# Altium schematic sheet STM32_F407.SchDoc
size A2
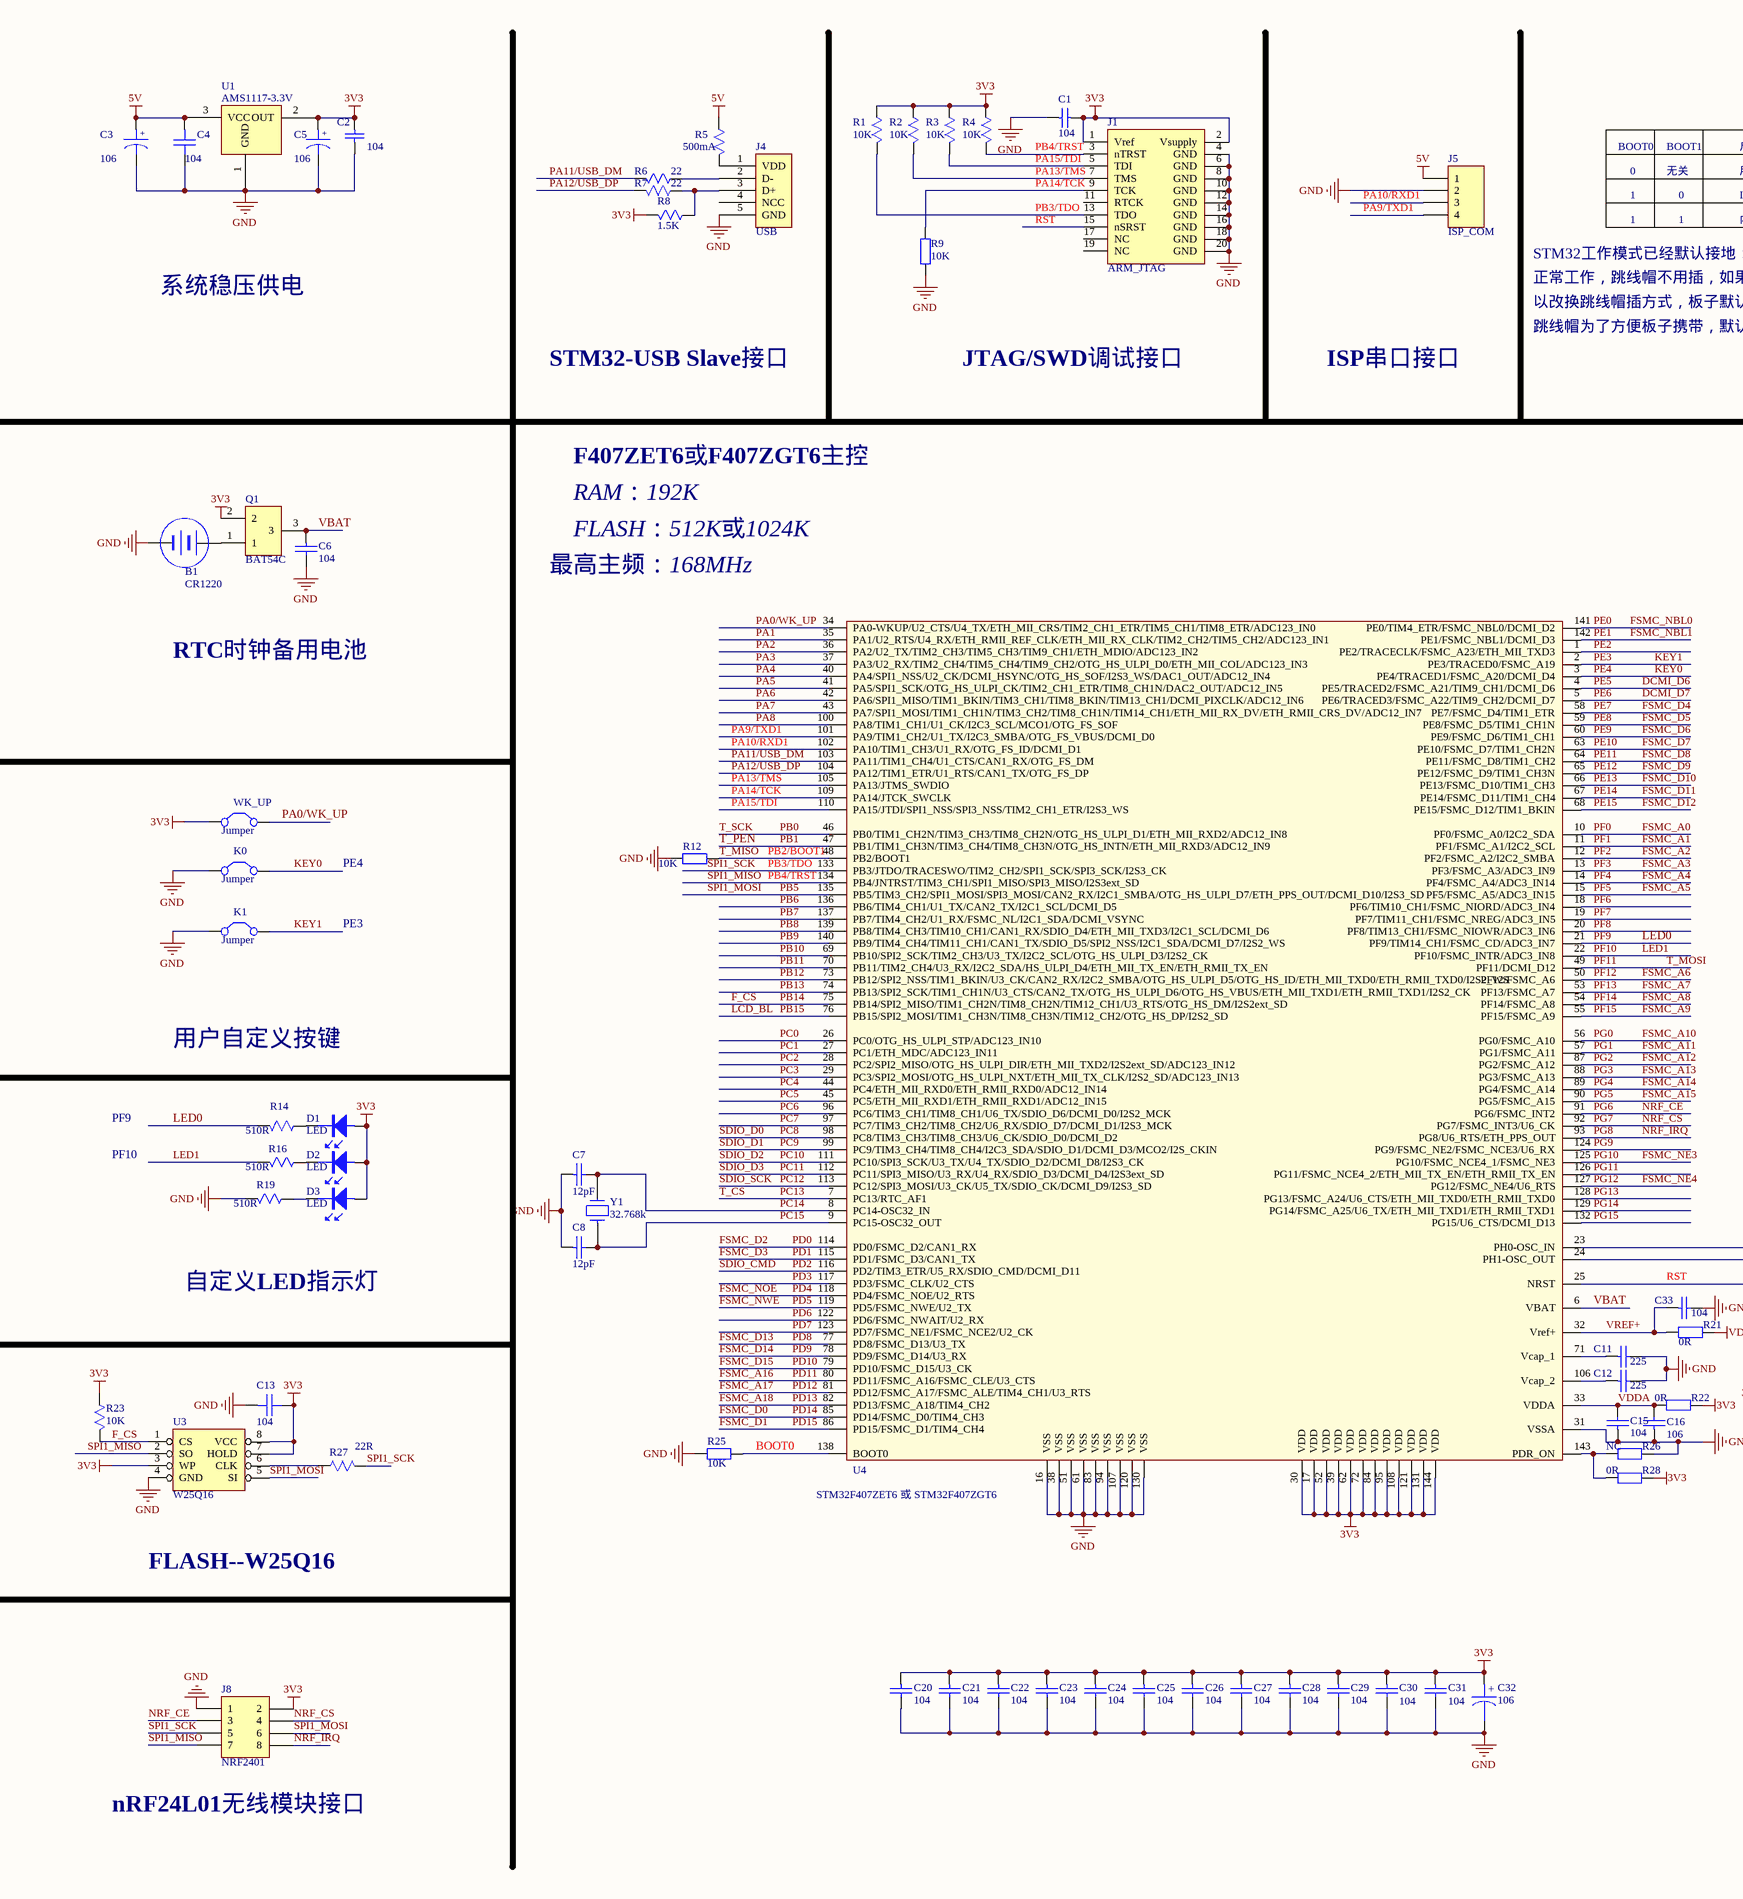
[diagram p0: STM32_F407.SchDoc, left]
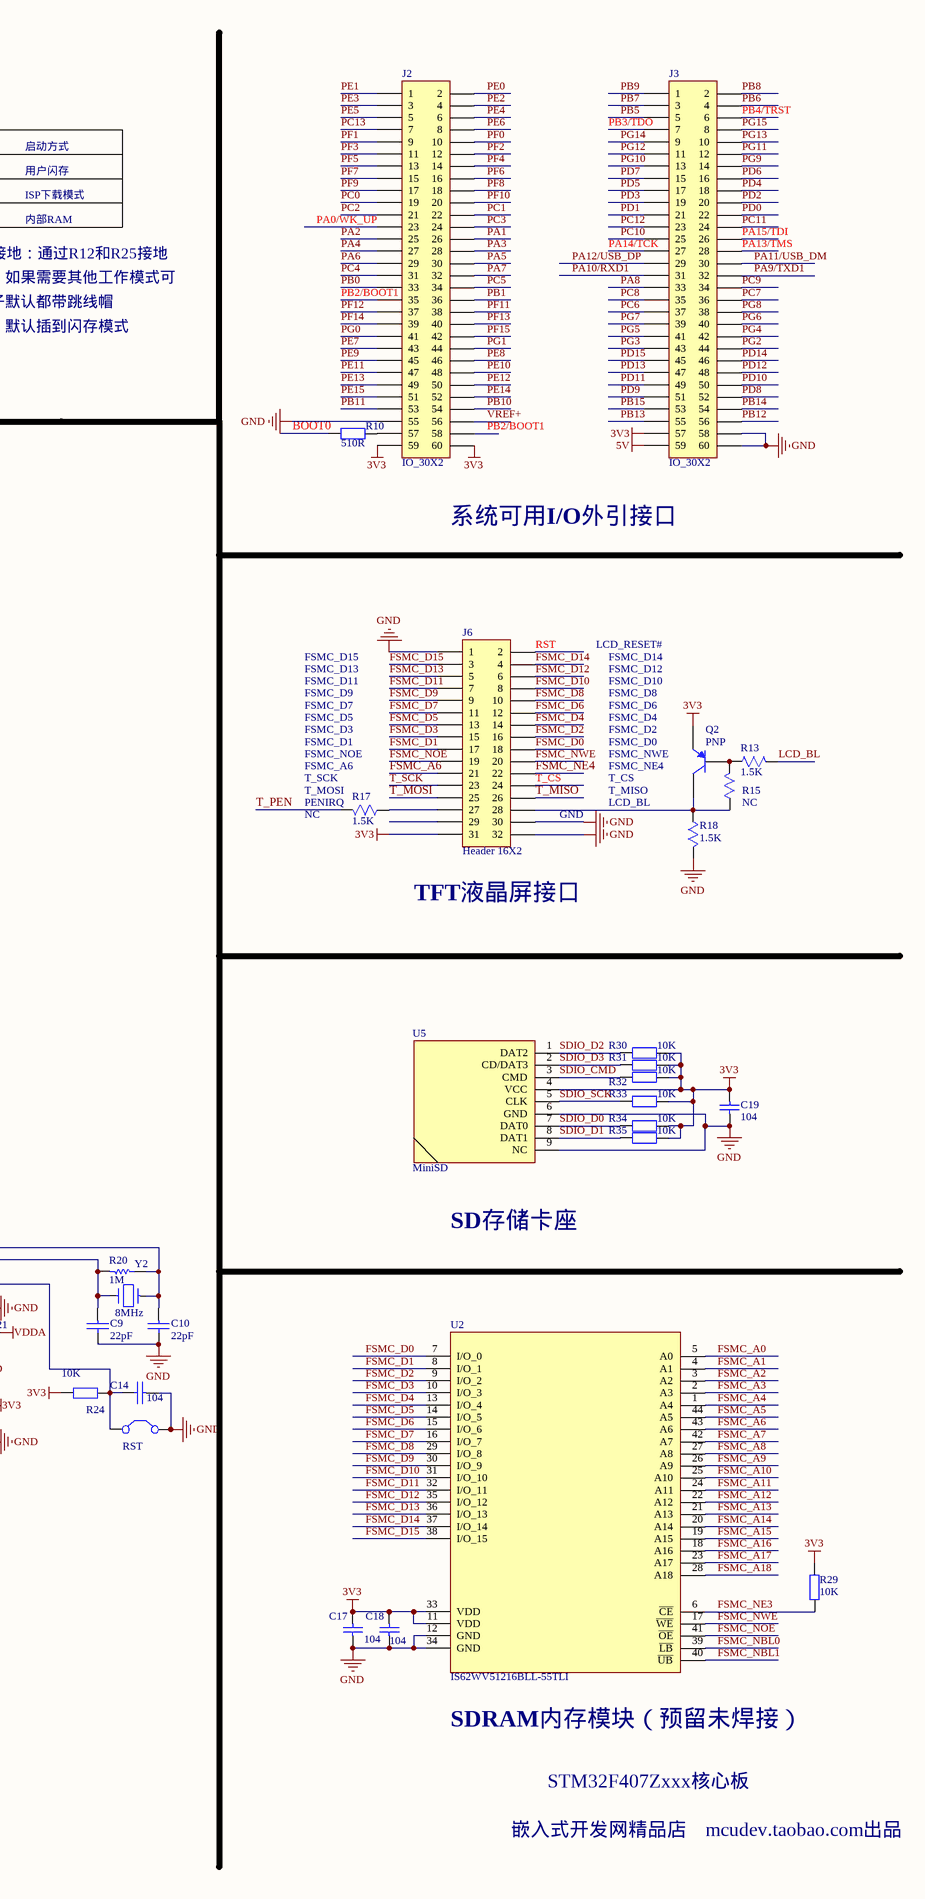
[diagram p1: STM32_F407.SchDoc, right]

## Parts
B1  CR1220  [CP1220]
C1  104  [RC0603]
C2  104  [RC0603]
C3  106  [RC0805]
C4  104  [RC0603]
C5  106  [RC0805]
C6  104  [RC0603]
C7  12pF  [RC0603]
C8  12pF  [RC0603]
C9  22pF  [RC0603]
C10  22pF  [RC0603]
C11  225  [RC0805]
C12  225  [RC0805]
C13  104  [RC0603]
C14  104  [RC0603]
C15  104  [RC0603]
C16  106  [RC0805]
C17  104  [RC0603]
C18  104  [RC0603]
C19  104  [RC0603]
C20  104  [RC0603]
C21  104  [RC0603]
C22  104  [RC0603]
C23  104  [RC0603]
C24  104  [RC0603]
C25  104  [RC0603]
C26  104  [RC0603]
C27  104  [RC0603]
C28  104  [RC0603]
C29  104  [RC0603]
C30  104  [RC0603]
C31  104  [RC0603]
C32  106  [RC0805]
C33  104  [RC0603]
D1  LED  [LED0805]
D2  LED  [LED0805]
D3  LED  [LED0805]
J1  ARM_JTAG  [JTAG20P]
J2  IO_30X2  [IDE2X30]
J3  IO_30X2  [IDE2X30]
J4  USB  [MINUSB]
J5  ISP_COM  [HDR1X4]
J6  Header 16X2  [IDE2X16-2.54]
J8  NRF2401  [DIP2X4-2.54]
K0  Jumper  [key]
K1  Jumper  [key]
Q1  BAT54C  [BAT54C]
Q2  PNP  [PNP_SOT23]
R1  10K  [RC0603]
R2  10K  [RC0603]
R3  10K  [RC0603]
R4  10K  [RC0603]
R5  500mA  [RC0805]
R6  22  [RC0603]
R7  22  [RC0603]
R8  1.5K  [RC0603]
R9  10K  [RC0603]
R10  510R  [RC0603]
R12  10K  [RC0603]
R13  1.5K  [RC0603]
R14  510R  [RC0603]
R15  NC  [RC0603]
R16  510R  [RC0603]
R17  1.5K  [RC0603]
R18  1.5K  [RC0603]
R19  510R  [RC0603]
R20  1M  [RC0603]
R21  0R  [RC0603]
R22  0R  [RC0603]
R23  10K  [RC0603]
R24  10K  [RC0603]
R25  10K  [RC0603]
R26  NC  [RC0603]
R27  22R  [RC0603]
R28  0R  [RC0603]
R29  10K  [RC0603]
R30  10K  [RC0603]
R31  10K  [RC0603]
R32  10K  [RC0603]
R33  10K  [RC0603]
R34  10K  [RC0603]
R35  10K  [RC0603]
RST  Key  [key]  (value not drawn)
U1  AMS1117-3.3V  [SOT223]
U2  IS62WV51216BLL-55TLI  [TSOP44]
U3  W25Q16  [SOIC8P]
U4  STM32F407ZET6 或 STM32F407ZGT6  [LQFP144N]
U5  MiniSD  [TF_SD]
WK_UP  Jumper  [key]
Y1  32.768k  [32.768k]
Y2  8MHz  [SMD49S]

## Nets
3V3: C1.2 C2.1 C5.1 C13.2 C17.2 C18.2 C19.1 C20.1 C21.1 C22.1 C23.1 C24.1 C25.1 C26.1 C27.1 C28.1 C29.1 C30.1 C31.1 C32.1 D1.1 D2.1 D3.1 J1.1(Vref) J1.2(Vsupply) J2.59 J2.60 J3.57 J6.31 J8.2 Q1.2 Q2.2(E) R1.1 R2.1 R3.1 R4.1 R8.2 R22.2 R23.1 R24.2 R28.2 R29.2 R30.2 R31.2 R32.2 R33.2 R34.2 R35.2 U1.2(OUT) U2.11(VDD) U2.33(VDD) U3.3(WP) U3.7(HOLD) U3.8(VCC) U4.17(VDD) U4.30(VDD) U4.39(VDD) U4.52(VDD) U4.62(VDD) U4.72(VDD) U4.84(VDD) U4.95(VDD) U4.108(VDD) U4.121(VDD) U4.131(VDD) U4.144(VDD) U5.4(VCC) WK_UP.1(C1)
5V: C3.1 C4.1 J3.59 J5.1 R5.1 U1.3(VCC)
GND: B1.2(-) C1.1 C2.2 C3.2 C4.2 C5.2 C6.2 C7.1 C8.1 C9.2 C10.2 C11.2 C12.2 C13.1 C14.1 C15.1 C16.1 C17.1 C18.1 C19.2 C20.2 C21.2 C22.2 C23.2 C24.2 C25.2 C26.2 C27.2 C28.2 C29.2 C30.2 C31.2 C32.2 C33.2 J1.4(GND) J1.6(GND) J1.8(GND) J1.10(GND) J1.12(GND) J1.14(GND) J1.16(GND) J1.18(GND) J1.20(GND) J2.55 J3.58 J3.60 J4.5(GND) J5.2 J6.1 J6.30 J6.32 J8.1 K0.1(C1) K1.1(C1) R9.1 R12.2 R18.2 R19.2 R25.2 R26.2 RST.2(C2) U1.1(GND) U2.12(GND) U2.34(GND) U3.4(GND) U4.16(VSS) U4.31(VSSA) U4.38(VSS) U4.51(VSS) U4.61(VSS) U4.83(VSS) U4.94(VSS) U4.107(VSS) U4.120(VSS) U4.130(VSS) U5.6(GND) U5.9(NC)
VDDA: C15.2 C16.2 R21.2 R22.1 U4.33(VDDA)
BOOT0: R10.2 R25.1 U4.138(BOOT0)
DCMI_D6: J2.5 U4.4(PE5/TRACED2/FSMC_A21/TIM9_CH1/DCMI_D6)  [also labelled PE5]
DCMI_D7: J2.8 U4.5(PE6/TRACED3/FSMC_A22/TIM9_CH2/DCMI_D7)  [also labelled PE6]
F_CS: J3.54 R23.2 U3.1(CS) U4.75(PB14/SPI2_MISO/TIM1_CH2N/TIM8_CH2N/TIM12_CH1/U3_RTS/OTG_HS_DM/I2S2ext_SD)  [also labelled PB14]
FSMC_A0: J2.10 U2.5(A0) U4.10(PF0/FSMC_A0/I2C2_SDA)  [also labelled PF0]
FSMC_A1: J2.9 U2.4(A1) U4.11(PF1/FSMC_A1/I2C2_SCL)  [also labelled PF1]
FSMC_A2: J2.12 U2.3(A2) U4.12(PF2/FSMC_A2/I2C2_SMBA)  [also labelled PF2]
FSMC_A3: J2.11 U2.2(A3) U4.13(PF3/FSMC_A3/ADC3_IN9)  [also labelled PF3]
FSMC_A4: J2.14 U2.1(A4) U4.14(PF4/FSMC_A4/ADC3_IN14)  [also labelled PF4]
FSMC_A5: J2.13 U2.44(A5) U4.15(PF5/FSMC_A5/ADC3_IN15)  [also labelled PF5]
FSMC_A6: J2.37 J6.21 U2.43(A6) U4.50(PF12/FSMC_A6)  [also labelled PF12]
FSMC_A7: J2.40 U2.42(A7) U4.53(PF13/FSMC_A7)  [also labelled PF13]
FSMC_A8: J2.39 U2.27(A8) U4.54(PF14/FSMC_A8)  [also labelled PF14]
FSMC_A9: J2.42 U2.26(A9) U4.55(PF15/FSMC_A9)  [also labelled PF15]
FSMC_A10: J2.41 U2.25(A10) U4.56(PG0/FSMC_A10)  [also labelled PG0]
FSMC_A11: J2.44 U2.24(A11) U4.57(PG1/FSMC_A11)  [also labelled PG1]
FSMC_A12: J3.44 U2.22(A12) U4.87(PG2/FSMC_A12)  [also labelled PG2]
FSMC_A13: J3.43 U2.21(A13) U4.88(PG3/FSMC_A13)  [also labelled PG3]
FSMC_A14: J3.42 U2.20(A14) U4.89(PG4/FSMC_A14)  [also labelled PG4]
FSMC_A15: J3.41 U2.19(A15) U4.90(PG5/FSMC_A15)  [also labelled PG5]
FSMC_A16: J3.49 U2.18(A16) U4.80(PD11/FSMC_A16/FSMC_CLE/U3_CTS)  [also labelled PD11]
FSMC_A17: J3.48 U2.23(A17) U4.81(PD12/FSMC_A17/FSMC_ALE/TIM4_CH1/U3_RTS)  [also labelled PD12]
FSMC_A18: J3.47 U2.28(A18) U4.82(PD13/FSMC_A18/TIM4_CH2)  [also labelled PD13]
FSMC_D0: J3.46 J6.18 U2.7(I/O_0) U4.85(PD14/FSMC_D0/TIM4_CH3)  [also labelled PD14]
FSMC_D1: J3.45 J6.17 U2.8(I/O_1) U4.86(PD15/FSMC_D1/TIM4_CH4)  [also labelled PD15]
FSMC_D2: J3.22 J6.16 U2.9(I/O_2) U4.114(PD0/FSMC_D2/CAN1_RX)  [also labelled PD0]
FSMC_D3: J3.21 J6.15 U2.10(I/O_3) U4.115(PD1/FSMC_D3/CAN1_TX)  [also labelled PD1]
FSMC_D4: J2.43 J6.14 U2.13(I/O_4) U4.58(PE7/FSMC_D4/TIM1_ETR)  [also labelled PE7]
FSMC_D5: J2.46 J6.13 U2.14(I/O_5) U4.59(PE8/FSMC_D5/TIM1_CH1N)  [also labelled PE8]
FSMC_D6: J2.45 J6.12 U2.15(I/O_6) U4.60(PE9/FSMC_D6/TIM1_CH1)  [also labelled PE9]
FSMC_D7: J2.48 J6.11 U2.16(I/O_7) U4.63(PE10/FSMC_D7/TIM1_CH2N)  [also labelled PE10]
FSMC_D8: J2.47 J6.10 U2.29(I/O_8) U4.64(PE11/FSMC_D8/TIM1_CH2)  [also labelled PE11]
FSMC_D9: J2.50 J6.9 U2.30(I/O_9) U4.65(PE12/FSMC_D9/TIM1_CH3N)  [also labelled PE12]
FSMC_D10: J2.49 J6.8 U2.31(I/O_10) U4.66(PE13/FSMC_D10/TIM1_CH3)  [also labelled PE13]
FSMC_D11: J2.52 J6.7 U2.32(I/O_11) U4.67(PE14/FSMC_D11/TIM1_CH4)  [also labelled PE14]
FSMC_D12: J2.51 J6.6 U2.35(I/O_12) U4.68(PE15/FSMC_D12/TIM1_BKIN)  [also labelled PE15]
FSMC_D13: J3.52 J6.5 U2.36(I/O_13) U4.77(PD8/FSMC_D13/U3_TX)  [also labelled PD8]
FSMC_D14: J3.51 J6.4 U2.37(I/O_14) U4.78(PD9/FSMC_D14/U3_RX)  [also labelled PD9]
FSMC_D15: J3.50 J6.3 U2.38(I/O_15) U4.79(PD10/FSMC_D15/U3_CK)  [also labelled PD10]
FSMC_NBL0: J2.2 U2.39(~{LB}) U4.141(PE0/TIM4_ETR/FSMC_NBL0/DCMI_D2)  [also labelled PE0]
FSMC_NBL1: J2.1 U2.40(~{UB}) U4.142(PE1/FSMC_NBL1/DCMI_D3)  [also labelled PE1]
FSMC_NE3: J3.13 R29.1 U2.6(~{CE}) U4.125(PG10/FSMC_NCE4_1/FSMC_NE3)  [also labelled PG10]
FSMC_NE4: J3.11 J6.22 U4.127(PG12/FSMC_NE4/U6_RTS)  [also labelled PG12]
FSMC_NOE: J3.18 J6.19 U2.41(~{OE}) U4.118(PD4/FSMC_NOE/U2_RTS)  [also labelled PD4]
FSMC_NWE: J3.17 J6.20 U2.17(~{WE}) U4.119(PD5/FSMC_NWE/U2_TX)  [also labelled PD5]
KEY0: J2.6 K0.2(C2) U4.3(PE4/TRACED1/FSMC_A20/DCMI_D4)  [also labelled PE4]
KEY1: J2.3 K1.2(C2) U4.2(PE3/TRACED0/FSMC_A19)  [also labelled PE3]
LCD_BL: J3.53 R13.2 U4.76(PB15/SPI2_MOSI/TIM1_CH3N/TIM8_CH3N/TIM12_CH2/OTG_HS_DP/I2S2_SD)  [also labelled PB15]
LED0: J2.17 R14.2 U4.21(PF9/TIM14_CH1/FSMC_CD/ADC3_IN7)  [also labelled PF9]
LED1: J2.20 R16.2 U4.22(PF10/FSMC_INTR/ADC3_IN8)  [also labelled PF10]
NRF_CE: J3.40 J8.3 U4.91(PG6/FSMC_INT2)  [also labelled PG6]
NRF_CS: J3.39 J8.4 U4.92(PG7/FSMC_INT3/U6_CK)  [also labelled PG7]
NRF_IRQ: J3.38 J8.8 U4.93(PG8/U6_RTS/ETH_PPS_OUT)  [also labelled PG8]
PA0/WK_UP: J2.23 U4.34(PA0-WKUP/U2_CTS/U4_TX/ETH_MII_CRS/TIM2_CH1_ETR/TIM5_CH1/TIM8_ETR/ADC123_IN0) WK_UP.2(C2)
PA1: J2.26 U4.35(PA1/U2_RTS/U4_RX/ETH_RMII_REF_CLK/ETH_MII_RX_CLK/TIM2_CH2/TIM5_CH2/ADC123_IN1)
PA2: J2.25 U4.36(PA2/U2_TX/TIM2_CH3/TIM5_CH3/TIM9_CH1/ETH_MDIO/ADC123_IN2)
PA3: J2.28 U4.37(PA3/U2_RX/TIM2_CH4/TIM5_CH4/TIM9_CH2/OTG_HS_ULPI_D0/ETH_MII_COL/ADC123_IN3)
PA4: J2.27 U4.40(PA4/SPI1_NSS/U2_CK/DCMI_HSYNC/OTG_HS_SOF/I2S3_WS/DAC1_OUT/ADC12_IN4)
PA5: J2.30 U4.41(PA5/SPI1_SCK/OTG_HS_ULPI_CK/TIM2_CH1_ETR/TIM8_CH1N/DAC2_OUT/ADC12_IN5)
PA6: J2.29 U4.42(PA6/SPI1_MISO/TIM1_BKIN/TIM3_CH1/TIM8_BKIN/TIM13_CH1/DCMI_PIXCLK/ADC12_IN6)
PA7: J2.32 U4.43(PA7/SPI1_MOSI/TIM1_CH1N/TIM3_CH2/TIM8_CH1N/TIM14_CH1/ETH_MII_RX_DV/ETH_RMII_CRS_DV/ADC12_IN7)
PA8: J3.33 U4.100(PA8/TIM1_CH1/U1_CK/I2C3_SCL/MCO1/OTG_FS_SOF)
PA9/TXD1: J3.32 J5.4 U4.101(PA9/TIM1_CH2/U1_TX/I2C3_SMBA/OTG_FS_VBUS/DCMI_D0)
PA10/RXD1: J3.31 J5.3 U4.102(PA10/TIM1_CH3/U1_RX/OTG_FS_ID/DCMI_D1)
PA11/USB_DM: J3.30 R6.2 U4.103(PA11/TIM1_CH4/U1_CTS/CAN1_RX/OTG_FS_DM)
PA12/USB_DP: J3.29 R7.2 U4.104(PA12/TIM1_ETR/U1_RTS/CAN1_TX/OTG_FS_DP)
PA13/TMS: J1.7(TMS) J3.28 R2.2 U4.105(PA13/JTMS_SWDIO)
PA14/TCK: J1.9(TCK) J3.27 R9.2 U4.109(PA14/JTCK_SWCLK)
PA15/TDI: J1.5(TDI) J3.26 R3.2 U4.110(PA15/JTDI/SPI1_NSS/SPI3_NSS/TIM2_CH1_ETR/I2S3_WS)
PB0: J2.33 J6.23 U4.46(PB0/TIM1_CH2N/TIM3_CH3/TIM8_CH2N/OTG_HS_ULPI_D1/ETH_MII_RXD2/ADC12_IN8)  [also labelled T_SCK]
PB1: J2.36 R17.2 U4.47(PB1/TIM1_CH3N/TIM3_CH4/TIM8_CH3N/OTG_HS_INTN/ETH_MII_RXD3/ADC12_IN9)  [also labelled T_PEN]
PB2/BOOT1: J2.35 J2.58 J6.26 R12.1 U4.48(PB2/BOOT1)  [also labelled T_MISO]
PB3/TDO: J1.13(TDO) J3.7 J8.5 R1.2 R27.2 U4.133(PB3/JTDO/TRACESWO/TIM2_CH2/SPI1_SCK/SPI3_SCK/I2S3_CK)  [also labelled SPI1_SCK]
PB4/TRST: J1.3(nTRST) J3.6 J8.7 R4.2 U3.2(SO) U4.134(PB4/JNTRST/TIM3_CH1/SPI1_MISO/SPI3_MISO/I2S3ext_SD)  [also labelled SPI1_MISO]
PB5: J3.5 J8.6 U3.5(SI) U4.135(PB5/TIM3_CH2/SPI1_MOSI/SPI3_MOSI/CAN2_RX/I2C1_SMBA/OTG_HS_ULPI_D7/ETH_PPS_OUT/DCMI_D10/I2S3_SD)  [also labelled SPI1_MOSI]
PB6: J3.4 U4.136(PB6/TIM4_CH1/U1_TX/CAN2_TX/I2C1_SCL/DCMI_D5)
PB7: J3.3 U4.137(PB7/TIM4_CH2/U1_RX/FSMC_NL/I2C1_SDA/DCMI_VSYNC)
PB8: J3.2 U4.139(PB8/TIM4_CH3/TIM10_CH1/CAN1_RX/SDIO_D4/ETH_MII_TXD3/I2C1_SCL/DCMI_D6)
PB9: J3.1 U4.140(PB9/TIM4_CH4/TIM11_CH1/CAN1_TX/SDIO_D5/SPI2_NSS/I2C1_SDA/DCMI_D7/I2S2_WS)
PB10: J2.54 U4.69(PB10/SPI2_SCK/TIM2_CH3/U3_TX/I2C2_SCL/OTG_HS_ULPI_D3/I2S2_CK)
PB11: J2.53 U4.70(PB11/TIM2_CH4/U3_RX/I2C2_SDA/HS_ULPI_D4/ETH_MII_TX_EN/ETH_RMII_TX_EN)
PB12: J3.56 U4.73(PB12/SPI2_NSS/TIM1_BKIN/U3_CK/CAN2_RX/I2C2_SMBA/OTG_HS_ULPI_D5/OTG_HS_ID/ETH_MII_TXD0/ETH_RMII_TXD0/I2S2_WS)
PB13: J3.55 U4.74(PB13/SPI2_SCK/TIM1_CH1N/U3_CTS/CAN2_TX/OTG_HS_ULPI_D6/OTG_HS_VBUS/ETH_MII_TXD1/ETH_RMII_TXD1/I2S2_CK)
PC0: J2.19 U4.26(PC0/OTG_HS_ULPI_STP/ADC123_IN10)
PC1: J2.22 U4.27(PC1/ETH_MDC/ADC123_IN11)
PC2: J2.21 U4.28(PC2/SPI2_MISO/OTG_HS_ULPI_DIR/ETH_MII_TXD2/I2S2ext_SD/ADC123_IN12)
PC3: J2.24 U4.29(PC3/SPI2_MOSI/OTG_HS_ULPI_NXT/ETH_MII_TX_CLK/I2S2_SD/ADC123_IN13)
PC4: J2.31 U4.44(PC4/ETH_MII_RXD0/ETH_RMII_RXD0/ADC12_IN14)
PC5: J2.34 U4.45(PC5/ETH_MII_RXD1/ETH_RMII_RXD1/ADC12_IN15)
PC6: J3.37 U4.96(PC6/TIM3_CH1/TIM8_CH1/U6_TX/SDIO_D6/DCMI_D0/I2S2_MCK)
PC7: J3.36 U4.97(PC7/TIM3_CH2/TIM8_CH2/U6_RX/SDIO_D7/DCMI_D1/I2S3_MCK)
PC8: J3.35 R34.1 U4.98(PC8/TIM3_CH3/TIM8_CH3/U6_CK/SDIO_D0/DCMI_D2) U5.7(DAT0)  [also labelled SDIO_D0]
PC9: J3.34 R35.1 U4.99(PC9/TIM3_CH4/TIM8_CH4/I2C3_SDA/SDIO_D1/DCMI_D3/MCO2/I2S_CKIN) U5.8(DAT1)  [also labelled SDIO_D1]
PC10: J3.25 R30.1 U4.111(PC10/SPI3_SCK/U3_TX/U4_TX/SDIO_D2/DCMI_D8/I2S3_CK) U5.1(DAT2)  [also labelled SDIO_D2]
PC11: J3.24 R31.1 U4.112(PC11/SPI3_MISO/U3_RX/U4_RX/SDIO_D3/DCMI_D4/I2S3ext_SD) U5.2(CD/DAT3)  [also labelled SDIO_D3]
PC12: J3.23 R33.1 U4.113(PC12/SPI3_MOSI/U3_CK/U5_TX/SDIO_CK/DCMI_D9/I2S3_SD) U5.5(CLK)  [also labelled SDIO_SCK]
PC13: J2.7 J6.24 U4.7(PC13/RTC_AF1)  [also labelled T_CS]
PC14: C7.2 U4.8(PC14-OSC32_IN) Y1.2
PC15: C8.2 U4.9(PC15-OSC32_OUT) Y1.1
PD2: J3.20 R32.1 U4.116(PD2/TIM3_ETR/U5_RX/SDIO_CMD/DCMI_D11) U5.3(CMD)  [also labelled SDIO_CMD]
PD3: J3.19 U4.117(PD3/FSMC_CLK/U2_CTS)
PD6: J3.16 U4.122(PD6/FSMC_NWAIT/U2_RX)
PD7: J3.15 U4.123(PD7/FSMC_NE1/FSMC_NCE2/U2_CK)
PE2: J2.4 U4.1(PE2/TRACECLK/FSMC_A23/ETH_MII_TXD3)
PF6: J2.16 U4.18(PF6/TIM10_CH1/FSMC_NIORD/ADC3_IN4)
PF7: J2.15 U4.19(PF7/TIM11_CH1/FSMC_NREG/ADC3_IN5)
PF8: J2.18 U4.20(PF8/TIM13_CH1/FSMC_NIOWR/ADC3_IN6)
PF11: J2.38 J6.25 U4.49(PF11/DCMI_D12)  [also labelled T_MOSI]
PG9: J3.14 U4.124(PG9/FSMC_NE2/FSMC_NCE3/U6_RX)
PG11: J3.12 U4.126(PG11/FSMC_NCE4_2/ETH_MII_TX_EN/ETH_RMII_TX_EN)
PG13: J3.10 U4.128(PG13/FSMC_A24/U6_CTS/ETH_MII_TXD0/ETH_RMII_TXD0)
PG14: J3.9 U4.129(PG14/FSMC_A25/U6_TX/ETH_MII_TXD1/ETH_RMII_TXD1)
PG15: J3.8 U4.132(PG15/U6_CTS/DCMI_D13)
RST: C14.2 J1.15(nSRST) J6.2 R24.1 RST.1(C1) U4.25(NRST)
VBAT: C6.1 Q1.3 U4.6(VBAT)
VREF+: C33.1 J2.56 R21.1 U4.32(Vref+)
NetB1_1: B1.1(+) Q1.1
NetC9_1: C9.1 R20.2 U4.24(PH1-OSC_OUT) Y2.2
NetC10_1: C10.1 R20.1 U4.23(PH0-OSC_IN) Y2.1
NetC11_1: C11.1 U4.71(Vcap_1)
NetC12_1: C12.1 U4.106(Vcap_2)
NetD1_2: D1.2 R14.1
NetD2_2: D2.2 R16.1
NetD3_2: D3.2 R19.1
NetJ2_57: J2.57 R10.1
NetJ4_1: J4.1(VDD) R5.2
NetJ4_2: J4.2(D-) R6.1
NetJ4_3: J4.3(D+) R7.1 R8.1
NetJ6_27: J6.27 R17.1
NetJ6_28: J6.28 Q2.3(C) R15.1 R18.1
NetQ2_1: Q2.1(B) R13.1 R15.2
NetR26_1: R26.1 R28.1 U4.143(PDR_ON)
NetR27_1: R27.1 U3.6(CLK)

Not connected (* = marked no-connect by the designer): J1 11(RTCK) 17(NC) 19(NC); J4 4(NCC); J6 29

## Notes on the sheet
- BOOT0
- BOOT1
- 启动方式
- 0
- 1
- 无关
- 用户闪存
- ISP下载模式
- 内部RAM
- STM32工作模式已经默认接地：通过R12和R25接地
- 正常工作，跳线帽不用插，如果需要其他工作模式可
- 系统稳压供电
- 以改换跳线帽插方式，板子默认都带跳线帽
- 跳线帽为了方便板子携带，默认插到闪存模式
- STM32-USB Slave接口
- JTAG/SWD调试接口
- ISP串口接口
- F407ZET6或F407ZGT6主控
- RAM：192K
- 系统可用I/O外引接口
- 最高主频：168MHz
- FLASH：512K或1024K
- LCD_RESET#
- RTC时钟备用电池
- FSMC_D7
- FSMC_D9
- FSMC_D11
- FSMC_D13
- FSMC_D15
- FSMC_D6
- FSMC_D8
- FSMC_D10
- FSMC_D12
- FSMC_D14
- FSMC_NOE
- (near R17) FSMC_A6
- FSMC_D1
- FSMC_D3
- FSMC_D5
- FSMC_NE4
- (near Q2) FSMC_NWE
- (near Q2) FSMC_D0
- (near Q2) FSMC_D2
- FSMC_D4
- (near R17) NC
- (near R17) T_MOSI
- (near R17) PENIRQ
- (near R17) T_SCK
- GND
- T_MISO
- T_CS
- LCD_BL
- PE4
- PE3
- (near J6) TFT液晶屏接口
- 用户自定义按键
- PF9
- PF10
- SD存储卡座
- 自定义LED指示灯
- FLASH--W25Q16
- (near U2) SDRAM内存模块（预留未焊接）
- STM32F407Zxxx核心板
- (near J8) nRF24L01无线模块接口
- 嵌入式开发网精品店
- mcudev.taobao.com出品

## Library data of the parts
B1 = BATTERY
C1 C2 C17 C18 = Cap: Capacitor
C3 C5 = CAP2
C4 C13 = CAP
C6-C12 C14-C16 C20-C31 C33 = CAP: Capcitor
C19 = Cap Semi: Capacitor (Semiconductor SIM Model)
C32 = CAPACITOR POL: Capacitor
J1 = JTAG
J2 J3 = Header 30X2: Header, 30-Pin, Dual row
J5 = Header 4: Header, 4-Pin
J6 = Header 16X2: Header, 16-Pin, Dual row
J8 = Header 4X2: Header, 4-Pin, Dual row
K0 K1 RST WK_UP = Jumper: Jumper Wire
Q2 = PNP: PNP Bipolar Transistor
R1-R8 R13-R19 R23 R27 = RES
R9 R10 R12 R21 R22 R24-R26 R28-R35 = Res2: Resistor
R20 = Res1: Resistor
U1 = 11
U3 = W25X16
U4 = STM32F407ZET6
Y1 = CRYSTAL: Crystal 8MHz PLUG
Y2 = XTAL: Crystal Oscillator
